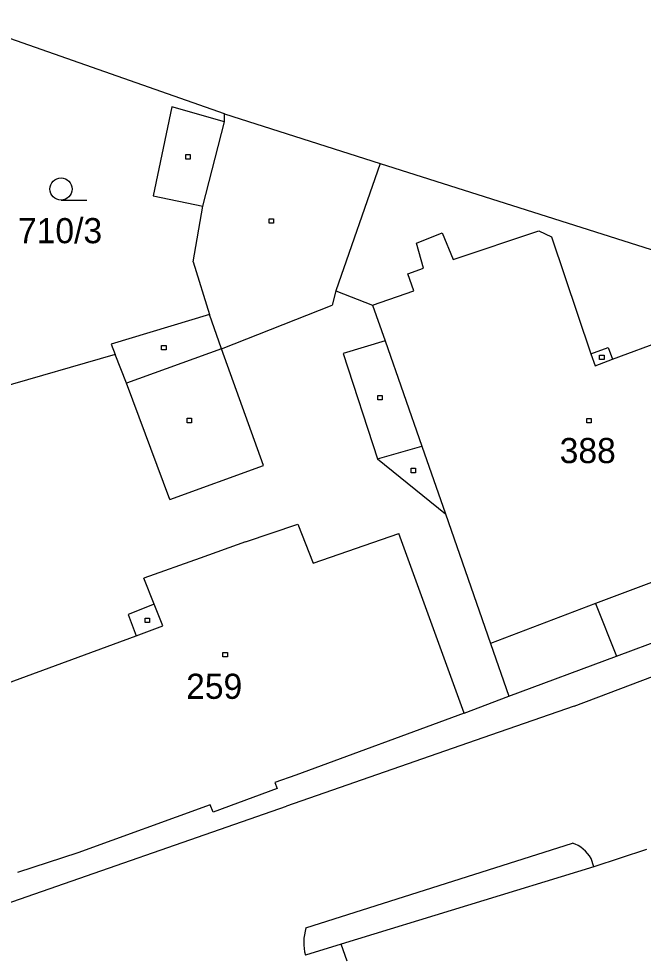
# Model space of a CAD drawing. Extents: x -711879 to -711361, y -1048782 to -1048177.
# Drawn here: x -711599.9 to -711557.6, y -1048524.9 to -1048461.6 of the extents above; entities that cross this region are included whole.
import ezdxf

# ---------------------------------------------------------------- set-up
doc = ezdxf.new("R2010")
doc.units = 0
for name, color, linetype in [('Vrstva 1', 7, 'Continuous'), ('Vrstva 14', 7, 'Continuous'), ('Vrstva 15', 7, 'Continuous'), ('Vrstva 2', 7, 'Continuous'), ('Vrstva 23', 7, 'Continuous'), ('Vrstva 25', 7, 'Continuous'), ('Vrstva 46', 7, 'Continuous')]:
    doc.layers.add(name, color=color, linetype=linetype)

msp = doc.modelspace()

# ---------------------------------------------------------------- linework, layer by layer
at = {"layer": 'Vrstva 1'}
for p, q in [((-711585.96, -1048468.04), (-711604.27, -1048461.61)), ((-711589.51, -1048467.56), (-711590.77, -1048473.59)), ((-711585.96, -1048468.59), (-711589.51, -1048467.56)), ((-711585.96, -1048468.59), (-711585.96, -1048468.04)), ((-711585.96, -1048468.04), (-711575.44, -1048471.4)), ((-711575.44, -1048471.4), (-711578.42, -1048480.01)), ((-711575.44, -1048471.4), (-711549.72, -1048479.57)), ((-711590.77, -1048473.59), (-711587.43, -1048474.28)), ((-711588.08, -1048478.06), (-711587.43, -1048474.28)), ((-711588.08, -1048478.06), (-711586.98, -1048481.62)), ((-711578.42, -1048480.01), (-711575.94, -1048480.97)), ((-711575.94, -1048480.97), (-711575.1, -1048483.4)), ((-711586.98, -1048481.62), (-711593.63, -1048483.61)), ((-711593.63, -1048483.61), (-711593.36, -1048484.32)), ((-711575.1, -1048483.4), (-711572.62, -1048490.51)), ((-711593.36, -1048484.32), (-711601.86, -1048486.76)), ((-711572.62, -1048490.51), (-711571.02, -1048495.1)), ((-711571.02, -1048495.1), (-711567.97, -1048503.86)), ((-711544.25, -1048494.85), (-711560.87, -1048501.16)), ((-711560.87, -1048501.16), (-711559.44, -1048504.71)), ((-711559.44, -1048504.71), (-711549.96, -1048501.2)), ((-711567.97, -1048503.86), (-711566.74, -1048507.41)), ((-711566.74, -1048507.41), (-711559.44, -1048504.71)), ((-711569.75, -1048508.56), (-711566.74, -1048507.41)), ((-711569.75, -1048508.56), (-711581.14, -1048512.77)), ((-711581.14, -1048512.77), (-711582.56, -1048513.26)), ((-711582.56, -1048513.26), (-711582.4, -1048513.67)), ((-711582.4, -1048513.67), (-711586.72, -1048515.27)), ((-711586.93, -1048514.76), (-711595.87, -1048518.02)), ((-711586.72, -1048515.27), (-711586.93, -1048514.76)), ((-711595.87, -1048518.02), (-711599.96, -1048519.34)), ((-711557.41, -1048517.79), (-711560.97, -1048518.96)), ((-711560.97, -1048518.96), (-711578.06, -1048524.2)), ((-711578.06, -1048524.2), (-711580.49, -1048524.94)), ((-711577.67, -1048525.33), (-711578.06, -1048524.2))]:
    msp.add_line(p, q, dxfattribs=at)
at = {"layer": 'Vrstva 2'}
for p, q in [((-711587.43, -1048474.28), (-711585.96, -1048468.59)), ((-711572.98, -1048476.78), (-711571.23, -1048476.08)), ((-711571.23, -1048476.08), (-711570.5, -1048477.9)), ((-711570.5, -1048477.9), (-711564.71, -1048475.95)), ((-711564.71, -1048475.95), (-711563.85, -1048476.35)), ((-711572.49, -1048478.47), (-711572.98, -1048476.78)), ((-711563.85, -1048476.35), (-711561.18, -1048484.27)), ((-711573.55, -1048478.86), (-711572.49, -1048478.47)), ((-711573.15, -1048480.02), (-711573.55, -1048478.86)), ((-711578.42, -1048480.01), (-711578.67, -1048480.97)), ((-711575.94, -1048480.97), (-711573.15, -1048480.02)), ((-711586.17, -1048483.93), (-711578.67, -1048480.97)), ((-711559.72, -1048484.64), (-711549.25, -1048480.75)), ((-711586.17, -1048483.93), (-711586.98, -1048481.62)), ((-711575.1, -1048483.4), (-711577.93, -1048484.24)), ((-711561.18, -1048484.27), (-711560.01, -1048483.84)), ((-711560.01, -1048483.84), (-711559.72, -1048484.64)), ((-711592.59, -1048486.25), (-711593.36, -1048484.32)), ((-711586.17, -1048483.93), (-711592.59, -1048486.25)), ((-711583.33, -1048491.81), (-711586.17, -1048483.93)), ((-711577.93, -1048484.24), (-711575.6, -1048491.38)), ((-711561.18, -1048484.27), (-711560.9, -1048485.09)), ((-711560.9, -1048485.09), (-711559.72, -1048484.64)), ((-711589.66, -1048494.12), (-711592.59, -1048486.25)), ((-711575.6, -1048491.38), (-711572.62, -1048490.51)), ((-711575.6, -1048491.38), (-711571.02, -1048495.1)), ((-711589.66, -1048494.12), (-711583.33, -1048491.81)), ((-711584.53, -1048496.98), (-711581, -1048495.79)), ((-711581, -1048495.79), (-711579.97, -1048498.43)), ((-711579.97, -1048498.43), (-711574.17, -1048496.42)), ((-711569.75, -1048508.56), (-711574.17, -1048496.42)), ((-711584.53, -1048496.98), (-711587.61, -1048498.09)), ((-711587.61, -1048498.09), (-711591.41, -1048499.44)), ((-711562.32, -1048508.09), (-711535.4, -1048497.92)), ((-711590.72, -1048501.19), (-711591.41, -1048499.44)), ((-711590.72, -1048501.19), (-711592.47, -1048501.89)), ((-711590.13, -1048502.67), (-711590.72, -1048501.19)), ((-711560.87, -1048501.16), (-711567.97, -1048503.86)), ((-711592.47, -1048501.89), (-711591.93, -1048503.34)), ((-711591.93, -1048503.34), (-711590.13, -1048502.67)), ((-711602.33, -1048507.17), (-711591.93, -1048503.34)), ((-711562.32, -1048508.09), (-711568.48, -1048510.24)), ((-711568.48, -1048510.24), (-711581.77, -1048514.86)), ((-711607.17, -1048523.7), (-711581.77, -1048514.86)), ((-711580.45, -1048523.09), (-711562.43, -1048517.35)), ((-711560.97, -1048518.96), (-711561.16, -1048518.4))]:
    msp.add_line(p, q, dxfattribs=at)
for centre, radius, start, end in [((-711563.211, -1048519.587), 2.369, 30.06775, 70.76629), ((-711577.226, -1048524.085), 3.374, 162.84581, 194.67692)]:
    msp.add_arc(centre, radius, start, end, dxfattribs=at)
at = {"layer": 'Vrstva 23'}
msp.add_line((-711597.01, -1048473.88), (-711595.26, -1048473.88), dxfattribs=at)
msp.add_circle((-711597.01, -1048473.13), 0.75, dxfattribs=at)
at = {"layer": 'Vrstva 25'}
for p, q in [((-711588.57, -1048470.8), (-711588.27, -1048470.8)), ((-711588.57, -1048471.1), (-711588.57, -1048470.8)), ((-711588.27, -1048471.1), (-711588.57, -1048471.1)), ((-711588.27, -1048470.8), (-711588.27, -1048471.1)), ((-711582.94, -1048475.13), (-711582.64, -1048475.13)), ((-711582.94, -1048475.43), (-711582.94, -1048475.13)), ((-711582.64, -1048475.43), (-711582.94, -1048475.43)), ((-711582.64, -1048475.13), (-711582.64, -1048475.43)), ((-711590.21, -1048483.7), (-711589.91, -1048483.7)), ((-711590.21, -1048484), (-711590.21, -1048483.7)), ((-711589.91, -1048483.7), (-711589.91, -1048484)), ((-711589.91, -1048484), (-711590.21, -1048484)), ((-711560.59, -1048484.35), (-711560.29, -1048484.35)), ((-711560.59, -1048484.65), (-711560.59, -1048484.35)), ((-711560.29, -1048484.35), (-711560.29, -1048484.65)), ((-711560.29, -1048484.65), (-711560.59, -1048484.65)), ((-711575.59, -1048487.08), (-711575.29, -1048487.08)), ((-711575.59, -1048487.38), (-711575.59, -1048487.08)), ((-711575.29, -1048487.38), (-711575.59, -1048487.38)), ((-711575.29, -1048487.08), (-711575.29, -1048487.38)), ((-711588.48, -1048488.63), (-711588.18, -1048488.63)), ((-711588.48, -1048488.93), (-711588.48, -1048488.63)), ((-711588.18, -1048488.93), (-711588.48, -1048488.93)), ((-711588.18, -1048488.63), (-711588.18, -1048488.93)), ((-711561.45, -1048488.64), (-711561.15, -1048488.64)), ((-711561.45, -1048488.94), (-711561.45, -1048488.64)), ((-711561.15, -1048488.94), (-711561.45, -1048488.94)), ((-711561.15, -1048488.64), (-711561.15, -1048488.94)), ((-711573.34, -1048492.01), (-711573.04, -1048492.01)), ((-711573.34, -1048492.31), (-711573.34, -1048492.01)), ((-711573.04, -1048492.01), (-711573.04, -1048492.31)), ((-711573.04, -1048492.31), (-711573.34, -1048492.31)), ((-711591.33, -1048502.14), (-711591.03, -1048502.14)), ((-711591.33, -1048502.44), (-711591.33, -1048502.14)), ((-711591.03, -1048502.14), (-711591.03, -1048502.44)), ((-711591.03, -1048502.44), (-711591.33, -1048502.44)), ((-711586.06, -1048504.47), (-711585.76, -1048504.47)), ((-711586.06, -1048504.77), (-711586.06, -1048504.47)), ((-711585.76, -1048504.77), (-711586.06, -1048504.77)), ((-711585.76, -1048504.47), (-711585.76, -1048504.77))]:
    msp.add_line(p, q, dxfattribs=at)
at = {"layer": 'Vrstva 46'}
for p, q in [((-711589.51, -1048467.56), (-711589.51, -1048467.56)), ((-711585.96, -1048468.59), (-711585.96, -1048468.59)), ((-711590.77, -1048473.59), (-711590.77, -1048473.59)), ((-711588.08, -1048478.06), (-711588.08, -1048478.06)), ((-711578.67, -1048480.97), (-711578.67, -1048480.97)), ((-711575.94, -1048480.97), (-711575.94, -1048480.97)), ((-711592.59, -1048486.25), (-711592.59, -1048486.25)), ((-711589.66, -1048494.12), (-711589.66, -1048494.12)), ((-711574.17, -1048496.42), (-711574.17, -1048496.42)), ((-711584.53, -1048496.98), (-711584.53, -1048496.98)), ((-711591.41, -1048499.44), (-711591.41, -1048499.44))]:
    msp.add_line(p, q, dxfattribs=at)

# ---------------------------------------------------------------- texts
at = {"layer": 'Vrstva 14'}
msp.add_text('710/3', height=1.7, dxfattribs=at).set_placement((-711599.92, -1048476.79))
at = {"layer": 'Vrstva 15'}
for s, p in [('388', (-711563.29, -1048491.66)), ('259', (-711588.55, -1048507.6))]:
    msp.add_text(s, height=1.7, dxfattribs=at).set_placement(p)

doc.saveas('drawing.dxf')
